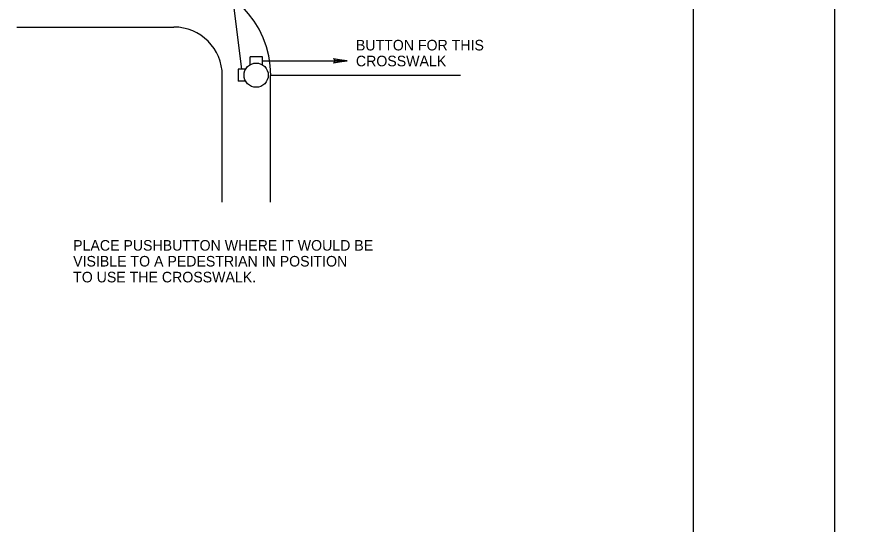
# Model space of a CAD drawing. Extents: x -344 to 940, y 22 to 1233.
# Drawn here: x -156.1 to 84.3, y 928.3 to 1072.1 of the extents above; entities that cross this region are included whole.
import ezdxf

# ---------------------------------------------------------------- set-up
doc = ezdxf.new("R2010")
doc.units = 0
for name, color, linetype in [('1', 7, 'Continuous'), ('2', 7, 'Continuous'), ('3', 7, 'Continuous'), ('PLT-BNDY', 7, 'Continuous')]:
    doc.layers.add(name, color=color, linetype=linetype)

# ---------------------------------------------------------------- blocks, each defined once
blk = doc.blocks.new('RARROW')
at = {"layer": '3'}
blk.add_lwpolyline([(-2.937125, 0.36875), (-2.82775, 0.156125), (0, 0), (-2.937125, 0.36875), (-3.08775, 0.497625), (0, 0), (-2.8255, -0.13975), (-2.928625, -0.350125), (0, 0), (-3.08775, -0.490625), (-2.928625, -0.350125)], dxfattribs=at)

msp = doc.modelspace()

# ---------------------------------------------------------------- linework, layer by layer
at = {"layer": '1'}
msp.add_line((75.86, 1195.17), (75.86, 631.17), dxfattribs=at)
at = {"layer": '2'}
for p, q in [((-92.34, 1057.29), (-96.94, 1093.87)), ((-156.14, 1069.2), (-111.64, 1069.2)), ((-89.94, 1058.54), (-89.94, 1060.79)), ((-86.44, 1060.79), (-89.94, 1060.79)), ((-86.44, 1058.54), (-86.44, 1060.79)), ((-86.44, 1059.64), (-62.43, 1059.64)), ((-91.19, 1057.29), (-93.32, 1057.29)), ((-93.32, 1057.29), (-93.32, 1053.91)), ((-97.89, 1019.58), (-97.89, 1055.45)), ((-91.19, 1053.91), (-93.32, 1053.91)), ((-84.14, 1019.58), (-84.14, 1055.45)), ((-30.27, 1055.45), (-84.14, 1055.45))]:
    msp.add_line(p, q, dxfattribs=at)
msp.add_circle((-88.25, 1055.58), 3.44, dxfattribs=at)
for radius in [27.5, 13.75]:
    msp.add_arc((-111.61, 1055.49), radius, 0, 90, dxfattribs=at)
at = {"layer": 'PLT-BNDY'}
msp.add_lwpolyline([(35.86, 1210.17), (876.86, 1210.17), (876.86, 616.17), (35.86, 616.17)], close=True, dxfattribs=at)

# ---------------------------------------------------------------- block references
at = {"layer": '2', "xscale": 1.2574347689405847, "yscale": 1.3092961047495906}
msp.add_blockref('RARROW', (-62.43, 1059.64), dxfattribs=at)

# ---------------------------------------------------------------- texts
at = {"layer": '2'}
for s, p in [('BUTTON FOR THIS', (-59.93, 1062.6)), ('CROSSWALK', (-59.93, 1058.1)), ('PLACE PUSHBUTTON WHERE IT WOULD BE', (-140.19, 1005.82)), ('VISIBLE TO A PEDESTRIAN IN POSITION', (-140.19, 1001.32)), ('TO USE THE CROSSWALK.', (-140.19, 996.82))]:
    msp.add_text(s, height=3, dxfattribs=at).set_placement(p)

doc.saveas('drawing.dxf')
